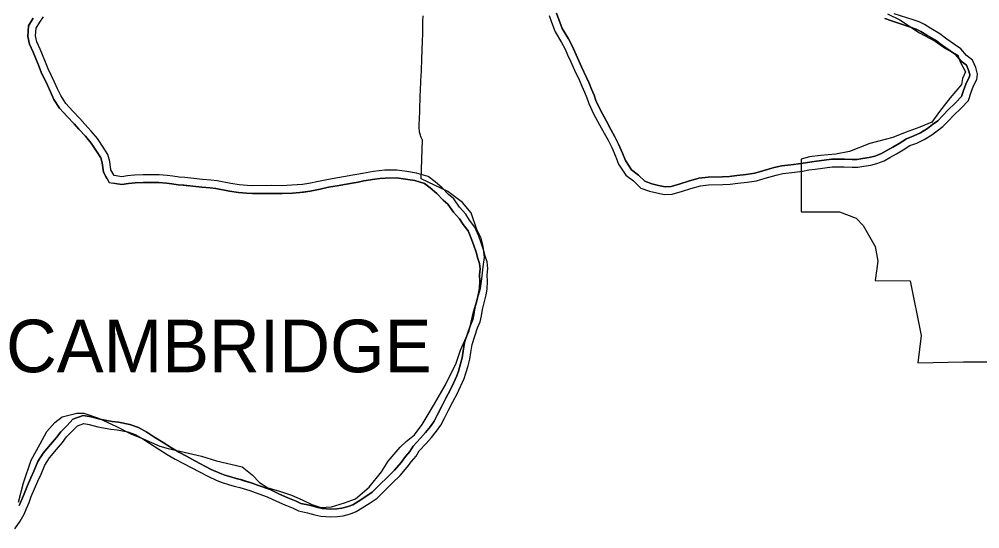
# Model space of a CAD drawing. Extents: x -29.6 to 34, y 0 to 22.
# Drawn here: x -25.281 to -23.658, y 3.715 to 4.576 of the extents above; entities that cross this region are included whole.
import ezdxf

# ---------------------------------------------------------------- set-up
doc = ezdxf.new("R2010")
doc.units = 0
for name, color, linetype in [('GM_X_Corporation', 7, 'Continuous'), ('GM_X_Corporation_Text', 7, 'Continuous'), ('GM_X_Major_River', 7, 'Continuous'), ('GM_X_Minor_River', 7, 'Continuous')]:
    doc.layers.add(name, color=color, linetype=linetype)

msp = doc.modelspace()

# ---------------------------------------------------------------- linework, layer by layer
at = {"layer": 'GM_X_Corporation'}
for points in [[(-25.2827, 3.7602), (-25.2741, 3.7929), (-25.2611, 3.831), (-25.2463, 3.8585), (-25.2346, 3.8795), (-25.2212, 3.8949), (-25.2088, 3.9042), (-25.1951, 3.9076), (-25.1841, 3.9107), (-25.1721, 3.9104), (-25.1473, 3.9021), (-25.1171, 3.888), (-25.0927, 3.8757), (-25.0721, 3.8671), (-25.0439, 3.8549), (-25.0298, 3.8508), (-25.0026, 3.8448), (-24.9734, 3.8377), (-24.9482, 3.8297), (-24.9049, 3.8196), (-24.8878, 3.8065), (-24.8757, 3.7934), (-24.8616, 3.7843), (-24.8434, 3.7793), (-24.8213, 3.7722), (-24.8031, 3.7642), (-24.787, 3.7561), (-24.7719, 3.7511), (-24.7538, 3.7521), (-24.7316, 3.7591), (-24.7132, 3.766), (-24.6903, 3.7853), (-24.6691, 3.8115), (-24.658, 3.8296), (-24.6379, 3.8528), (-24.6278, 3.8629), (-24.6137, 3.874), (-24.6006, 3.8911), (-24.5885, 3.9113), (-24.5795, 3.9264), (-24.5613, 3.9586), (-24.5432, 3.9949), (-24.5361, 4.0171), (-24.521, 4.0493), (-24.514, 4.0816), (-24.5019, 4.1211), (-24.4999, 4.1377), (-24.4973, 4.1579), (-24.4953, 4.1735), (-24.4973, 4.1926), (-24.5009, 4.2062), (-24.5084, 4.2209), (-24.5176, 4.2489), (-24.5322, 4.2665), (-24.5575, 4.285), (-24.6024, 4.3065), (-24.6002, 4.372), (-24.6005, 4.3726), (-24.6013, 4.3741), (-24.6021, 4.3761), (-24.6028, 4.3778), (-24.6035, 4.3799), (-24.604, 4.3816), (-24.6045, 4.3834), (-24.6049, 4.3853), (-24.6053, 4.3884), (-24.6055, 4.3907), (-24.6056, 4.3937), (-24.6056, 4.397), (-24.6055, 4.4007), (-24.6053, 4.4053), (-24.605, 4.4108), (-24.6048, 4.417), (-24.6045, 4.4229), (-24.6043, 4.4309), (-24.6039, 4.4378), (-24.6037, 4.4448), (-24.6027, 4.4698), (-24.6026, 4.4744), (-24.6024, 4.4786), (-24.6019, 4.4901), (-24.6012, 4.5081), (-24.6007, 4.5243), (-24.6002, 4.5385), (-24.5997, 4.5516), (-24.5995, 4.5637), (-24.5992, 4.5728), (-24.5989, 4.5818)], [(-23.8145, 4.5853), (-23.7934, 4.5751), (-23.7604, 4.5531), (-23.7338, 4.539), (-23.7165, 4.5265), (-23.6953, 4.5151), (-23.6914, 4.5041), (-23.6828, 4.4869), (-23.6875, 4.4759), (-23.6891, 4.4657), (-23.7087, 4.443), (-23.7267, 4.4202), (-23.7392, 4.4022), (-23.7596, 4.3935), (-23.7847, 4.3849), (-23.8051, 4.3763), (-23.8443, 4.3661), (-23.8788, 4.3527), (-23.9015, 4.348), (-23.9274, 4.3457), (-23.9462, 4.3433), (-23.9601, 4.3396), (-23.9601, 4.2508), (-23.8952, 4.2508), (-23.8674, 4.2397), (-23.8554, 4.2273), (-23.8353, 4.1923), (-23.8307, 4.1673), (-23.8354, 4.1346), (-23.776, 4.134), (-23.7577, 4.0418), (-23.7628, 3.9956), (-23.6858, 3.997), (-23.6371, 3.9973)]]:
    msp.add_lwpolyline(points, dxfattribs=at)
at = {"layer": 'GM_X_Major_River'}
for points in [[(-25.1327, 4.3056), (-25.1392, 4.3176), (-25.1413, 4.3332), (-25.1438, 4.3419), (-25.1506, 4.3529), (-25.1598, 4.3666), (-25.1695, 4.3782), (-25.1805, 4.3902), (-25.1885, 4.3995), (-25.2005, 4.4114), (-25.2133, 4.4255), (-25.2229, 4.4406), (-25.2287, 4.4532), (-25.2337, 4.4644), (-25.2442, 4.4866), (-25.2491, 4.4982), (-25.2541, 4.5107), (-25.258, 4.5203), (-25.2642, 4.5337), (-25.2671, 4.5469), (-25.2658, 4.5648), (-25.2577, 4.578)], [(-25.2577, 4.578), (-25.2658, 4.5648), (-25.2671, 4.5469), (-25.2642, 4.5337), (-25.258, 4.5203), (-25.2541, 4.5107), (-25.2491, 4.4982), (-25.2442, 4.4866), (-25.2337, 4.4644), (-25.2287, 4.4532), (-25.2229, 4.4406), (-25.2133, 4.4255), (-25.2005, 4.4114), (-25.1885, 4.3995), (-25.1805, 4.3902), (-25.1695, 4.3782), (-25.1598, 4.3666), (-25.1506, 4.3529), (-25.1438, 4.3419), (-25.1413, 4.3332), (-25.1392, 4.3176), (-25.1296, 4.2999)], [(-25.1212, 4.3118), (-25.1266, 4.3217), (-25.1285, 4.3359), (-25.1317, 4.3473), (-25.1396, 4.36), (-25.1493, 4.3745), (-25.1597, 4.3868), (-25.1707, 4.3988), (-25.1789, 4.4084), (-25.1911, 4.4204), (-25.2028, 4.4334), (-25.2114, 4.4469), (-25.2168, 4.4586), (-25.2219, 4.4699), (-25.2323, 4.4919), (-25.237, 4.5032), (-25.242, 4.5156), (-25.246, 4.5255), (-25.2518, 4.5379), (-25.2539, 4.5478), (-25.253, 4.5606), (-25.2467, 4.571), (-25.2407, 4.5799)], [(-24.3858, 4.5822), (-24.3818, 4.5708), (-24.3757, 4.5549), (-24.3649, 4.5365), (-24.3592, 4.5255), (-24.3549, 4.5156), (-24.3502, 4.5053), (-24.343, 4.4901), (-24.3347, 4.4724), (-24.3308, 4.4628), (-24.3264, 4.4529), (-24.3225, 4.443), (-24.3192, 4.4338), (-24.3109, 4.4164), (-24.3009, 4.3973), (-24.293, 4.3835), (-24.2865, 4.3715), (-24.2804, 4.3591), (-24.274, 4.3449), (-24.2689, 4.3314), (-24.2564, 4.3123), (-24.2436, 4.3028), (-24.2314, 4.2908), (-24.2165, 4.2856), (-24.2041, 4.2825), (-24.1913, 4.2798), (-24.1779, 4.2802), (-24.1609, 4.2853), (-24.1467, 4.29), (-24.1305, 4.2944), (-24.1167, 4.2963), (-24.0926, 4.2965), (-24.0802, 4.2973), (-24.0674, 4.2988), (-24.0515, 4.3007), (-24.0359, 4.3029), (-24.0211, 4.3073), (-24.0027, 4.3128), (-23.991, 4.3153), (-23.9758, 4.3169), (-23.9581, 4.3195), (-23.9475, 4.3213), (-23.9365, 4.3228), (-23.9078, 4.3266), (-23.8976, 4.3267), (-23.8876, 4.3264), (-23.8742, 4.3258), (-23.8646, 4.3262), (-23.8543, 4.3277), (-23.8427, 4.3296), (-23.8321, 4.3321), (-23.82, 4.3368), (-23.8102, 4.3422), (-23.7989, 4.3484), (-23.7876, 4.3552), (-23.7766, 4.3624), (-23.7646, 4.3667), (-23.7523, 4.3729), (-23.7396, 4.3808), (-23.7304, 4.3876), (-23.7209, 4.3948), (-23.7114, 4.4044), (-23.7029, 4.4134), (-23.6899, 4.4256), (-23.6776, 4.4388), (-23.6731, 4.453), (-23.6689, 4.4637), (-23.6633, 4.4744), (-23.662, 4.4833), (-23.6649, 4.4947), (-23.6706, 4.5067), (-23.6806, 4.5145), (-23.6906, 4.5261), (-23.7009, 4.5331), (-23.7138, 4.5423), (-23.7259, 4.5514), (-23.7412, 4.5602), (-23.7518, 4.5669), (-23.7611, 4.5714), (-23.771, 4.5749), (-23.803, 4.5853)], [(-24.3734, 4.5864), (-24.3696, 4.5753), (-24.3639, 4.5605), (-24.3535, 4.5428), (-24.3474, 4.5311), (-24.3429, 4.5209), (-24.3383, 4.5108), (-24.3312, 4.4956), (-24.3228, 4.4776), (-24.3187, 4.4679), (-24.3144, 4.4579), (-24.3102, 4.4476), (-24.3071, 4.4388), (-24.2993, 4.4223), (-24.2894, 4.4036), (-24.2816, 4.3898), (-24.2749, 4.3774), (-24.2686, 4.3647), (-24.2619, 4.3499), (-24.2572, 4.3374), (-24.2467, 4.3214), (-24.235, 4.3128), (-24.2243, 4.3022), (-24.2128, 4.2981), (-24.2011, 4.2952), (-24.1901, 4.2929), (-24.18, 4.2932), (-24.1648, 4.2978), (-24.1505, 4.3025), (-24.1331, 4.3072), (-24.1176, 4.3093), (-24.093, 4.3095), (-24.0814, 4.3103), (-24.069, 4.3118), (-24.0532, 4.3136), (-24.0387, 4.3157), (-24.0248, 4.3198), (-24.006, 4.3254), (-23.9931, 4.3282), (-23.9774, 4.3298), (-23.9602, 4.3324), (-23.9495, 4.3342), (-23.9382, 4.3358), (-23.9087, 4.3396), (-23.8974, 4.3397), (-23.8872, 4.3394), (-23.8742, 4.3388), (-23.8658, 4.3392), (-23.8563, 4.3406), (-23.8452, 4.3424), (-23.836, 4.3446), (-23.8256, 4.3487), (-23.8164, 4.3537), (-23.8054, 4.3597), (-23.7945, 4.3662), (-23.7825, 4.3741), (-23.7698, 4.3788), (-23.7586, 4.3843), (-23.7469, 4.3916), (-23.7382, 4.398), (-23.7295, 4.4046), (-23.7208, 4.4135), (-23.7122, 4.4226), (-23.6992, 4.4348), (-23.6892, 4.4455), (-23.6854, 4.4574), (-23.6808, 4.4691), (-23.6759, 4.4785), (-23.6753, 4.4827), (-23.6772, 4.4902), (-23.6811, 4.4983), (-23.6897, 4.5049), (-23.6994, 4.5163), (-23.7084, 4.5224), (-23.7215, 4.5318), (-23.7331, 4.5405), (-23.7479, 4.549), (-23.7582, 4.5554), (-23.7661, 4.5594), (-23.7752, 4.5625), (-23.8074, 4.573), (-23.8188, 4.5774)], [(-23.8188, 4.5774), (-23.8074, 4.573), (-23.7752, 4.5625), (-23.7661, 4.5594), (-23.7582, 4.5554), (-23.7479, 4.549), (-23.7331, 4.5405), (-23.7215, 4.5318), (-23.7084, 4.5224), (-23.6994, 4.5163), (-23.6897, 4.5049), (-23.6811, 4.4983), (-23.6772, 4.4902), (-23.6753, 4.4827), (-23.6759, 4.4785), (-23.6808, 4.4691), (-23.6854, 4.4574), (-23.6892, 4.4455), (-23.6992, 4.4348), (-23.7122, 4.4226), (-23.7208, 4.4135), (-23.7295, 4.4046), (-23.7382, 4.398), (-23.7469, 4.3916), (-23.7586, 4.3843), (-23.7698, 4.3788), (-23.7825, 4.3741), (-23.7945, 4.3662), (-23.8054, 4.3597), (-23.8164, 4.3537), (-23.8256, 4.3487), (-23.836, 4.3446), (-23.8452, 4.3424), (-23.8563, 4.3406), (-23.8658, 4.3392), (-23.8742, 4.3388), (-23.8872, 4.3394), (-23.8974, 4.3397), (-23.9087, 4.3396), (-23.9382, 4.3358), (-23.9495, 4.3342), (-23.9602, 4.3324), (-23.9774, 4.3298), (-23.9931, 4.3282), (-24.006, 4.3254), (-24.0248, 4.3198), (-24.0387, 4.3157), (-24.0532, 4.3136), (-24.069, 4.3118), (-24.0814, 4.3103), (-24.093, 4.3095), (-24.1176, 4.3093), (-24.1331, 4.3072), (-24.1505, 4.3025), (-24.1648, 4.2978), (-24.18, 4.2932), (-24.1901, 4.2929), (-24.2011, 4.2952), (-24.2128, 4.2981), (-24.2243, 4.3022), (-24.235, 4.3128), (-24.2467, 4.3214), (-24.2572, 4.3374), (-24.2619, 4.3499), (-24.2686, 4.3647), (-24.2749, 4.3774), (-24.2816, 4.3898), (-24.2894, 4.4036), (-24.2993, 4.4223), (-24.3071, 4.4388), (-24.3102, 4.4476), (-24.3144, 4.4579), (-24.3187, 4.4679), (-24.3228, 4.4776), (-24.3312, 4.4956), (-24.3383, 4.5108), (-24.3429, 4.5209), (-24.3474, 4.5311), (-24.3535, 4.5428), (-24.3639, 4.5605), (-24.3696, 4.5753), (-24.3734, 4.5864)], [(-24.9089, 3.785), (-24.8919, 3.7798), (-24.883, 3.7767), (-24.8624, 3.7694), (-24.8468, 3.762), (-24.8326, 3.7557), (-24.8187, 3.7498), (-24.8098, 3.7456), (-24.7942, 3.7421), (-24.7821, 3.739), (-24.7719, 3.7366), (-24.7552, 3.7353), (-24.7435, 3.7361), (-24.734, 3.7373), (-24.7219, 3.7402), (-24.712, 3.7442), (-24.7018, 3.7503), (-24.6887, 3.7589), (-24.6768, 3.7671), (-24.6627, 3.7811), (-24.6511, 3.7922), (-24.638, 3.8054), (-24.6261, 3.819), (-24.6184, 3.829), (-24.611, 3.838), (-24.6054, 3.8469), (-24.5938, 3.8594), (-24.585, 3.8694), (-24.5762, 3.8801), (-24.5692, 3.8901), (-24.5629, 3.9023), (-24.5562, 3.9154), (-24.5489, 3.9297), (-24.5415, 3.9433), (-24.5356, 3.9557), (-24.5297, 3.9689), (-24.5269, 3.9778), (-24.5231, 3.9903), (-24.5203, 4.0017), (-24.5186, 4.0131), (-24.5162, 4.0266), (-24.5069, 4.0547), (-24.5027, 4.065), (-24.5006, 4.0747), (-24.4986, 4.0857), (-24.4958, 4.0971), (-24.4924, 4.1102), (-24.491, 4.1202), (-24.49, 4.1334), (-24.4905, 4.1437), (-24.4895, 4.1547), (-24.491, 4.166), (-24.4939, 4.1756), (-24.4971, 4.1866), (-24.5011, 4.1983), (-24.5051, 4.2093), (-24.5116, 4.2249), (-24.5205, 4.2365), (-24.527, 4.2468), (-24.5377, 4.2584), (-24.5473, 4.2726), (-24.5562, 4.28), (-24.567, 4.2909), (-24.5787, 4.3015), (-24.5905, 4.3103), (-24.61, 4.3162), (-24.6267, 4.3189), (-24.6433, 4.3209), (-24.6639, 4.3208), (-24.6734, 4.3196), (-24.6826, 4.3185), (-24.7014, 4.3155), (-24.711, 4.3137), (-24.7212, 4.3118), (-24.7304, 4.3103), (-24.7467, 4.3074), (-24.7616, 4.3048), (-24.7757, 4.3018), (-24.7923, 4.2985), (-24.8026, 4.297), (-24.8207, 4.2955), (-24.8377, 4.2946), (-24.8547, 4.2949), (-24.8869, 4.2946), (-24.8965, 4.2949), (-24.9096, 4.2963), (-24.9238, 4.2983), (-24.9472, 4.3031), (-24.9575, 4.3041), (-24.9717, 4.3051), (-24.9866, 4.3067), (-25.0018, 4.3084), (-25.0114, 4.3094), (-25.022, 4.3107), (-25.0312, 4.3121), (-25.0451, 4.3131), (-25.072, 4.3132), (-25.0865, 4.3128), (-25.0985, 4.3112), (-25.1081, 4.3098), (-25.1212, 4.3118)], [(-25.1296, 4.2999), (-25.1081, 4.2965), (-25.0967, 4.2983), (-25.0855, 4.2997), (-25.0718, 4.3002), (-25.0456, 4.3), (-25.0326, 4.2991), (-25.0238, 4.2978), (-25.0129, 4.2964), (-25.0032, 4.2954), (-24.988, 4.2937), (-24.9728, 4.292), (-24.9586, 4.2911), (-24.9491, 4.2902), (-24.926, 4.2854), (-24.9112, 4.2833), (-24.8973, 4.2819), (-24.8871, 4.2816), (-24.8547, 4.2818), (-24.8374, 4.2816), (-24.8198, 4.2824), (-24.8011, 4.284), (-24.7901, 4.2856), (-24.7731, 4.289), (-24.7591, 4.292), (-24.7444, 4.2945), (-24.7282, 4.2975), (-24.719, 4.299), (-24.7086, 4.3008), (-24.6991, 4.3027), (-24.6808, 4.3056), (-24.6719, 4.3067), (-24.6631, 4.3077), (-24.6441, 4.3078), (-24.6285, 4.306), (-24.6129, 4.3034), (-24.5964, 4.2984), (-24.587, 4.2914), (-24.576, 4.2815), (-24.5651, 4.2704), (-24.5571, 4.2637), (-24.5479, 4.2503), (-24.5374, 4.2388), (-24.5312, 4.2291), (-24.523, 4.2183), (-24.5173, 4.2045), (-24.5134, 4.194), (-24.5096, 4.1826), (-24.5064, 4.1719), (-24.5038, 4.1633), (-24.5026, 4.1544), (-24.5036, 4.144), (-24.5031, 4.1336), (-24.504, 4.1216), (-24.5052, 4.1128), (-24.5085, 4.1003), (-24.5114, 4.0884), (-24.5134, 4.0772), (-24.5152, 4.0689), (-24.5191, 4.0592), (-24.5289, 4.0298), (-24.5315, 4.0152), (-24.5332, 4.0042), (-24.5357, 3.9937), (-24.5394, 3.9817), (-24.5419, 3.9736), (-24.5475, 3.9612), (-24.5532, 3.9492), (-24.5604, 3.9358), (-24.5679, 3.9214), (-24.5745, 3.9082), (-24.5804, 3.8969), (-24.5866, 3.888), (-24.5949, 3.8779), (-24.6035, 3.8681), (-24.6158, 3.8549), (-24.6216, 3.8456), (-24.6286, 3.8372), (-24.6362, 3.8273), (-24.6476, 3.8143), (-24.6602, 3.8015), (-24.6718, 3.7905), (-24.6851, 3.7772), (-24.696, 3.7697), (-24.7087, 3.7613), (-24.7178, 3.7559), (-24.7259, 3.7526), (-24.7363, 3.7501), (-24.7447, 3.7491), (-24.7551, 3.7484), (-24.7698, 3.7496), (-24.779, 3.7517), (-24.7912, 3.7549), (-24.8056, 3.758), (-24.8134, 3.7617), (-24.8274, 3.7677), (-24.8414, 3.7739), (-24.8575, 3.7815), (-24.8787, 3.789), (-24.8878, 3.7922), (-24.9054, 3.7976)], [(-24.9051, 3.7975), (-24.8878, 3.7922), (-24.8787, 3.789), (-24.8575, 3.7815), (-24.8414, 3.7739), (-24.8274, 3.7677), (-24.8134, 3.7617), (-24.8056, 3.758), (-24.7912, 3.7549), (-24.779, 3.7517), (-24.7698, 3.7496), (-24.7551, 3.7484), (-24.7447, 3.7491), (-24.7363, 3.7501), (-24.7259, 3.7526), (-24.7178, 3.7559), (-24.7087, 3.7613), (-24.696, 3.7697), (-24.6851, 3.7772), (-24.6718, 3.7905), (-24.6602, 3.8015), (-24.6476, 3.8143), (-24.6362, 3.8273), (-24.6286, 3.8372), (-24.6216, 3.8456), (-24.6158, 3.8549), (-24.6035, 3.8681), (-24.5949, 3.8779), (-24.5866, 3.888), (-24.5804, 3.8969), (-24.5745, 3.9082), (-24.5679, 3.9214), (-24.5604, 3.9358), (-24.5532, 3.9492), (-24.5475, 3.9612), (-24.5419, 3.9736), (-24.5394, 3.9817), (-24.5357, 3.9937), (-24.5332, 4.0042), (-24.5315, 4.0152), (-24.5289, 4.0298), (-24.5191, 4.0592), (-24.5152, 4.0689), (-24.5134, 4.0772), (-24.5114, 4.0884), (-24.5085, 4.1003), (-24.5052, 4.1128), (-24.504, 4.1216), (-24.5031, 4.1336), (-24.5036, 4.144), (-24.5026, 4.1544), (-24.5038, 4.1633), (-24.5064, 4.1719), (-24.5096, 4.1826), (-24.5134, 4.194), (-24.5173, 4.2045), (-24.523, 4.2183), (-24.5312, 4.2291), (-24.5374, 4.2388), (-24.5479, 4.2503), (-24.5571, 4.2637), (-24.5651, 4.2704), (-24.576, 4.2815), (-24.587, 4.2914), (-24.5964, 4.2984), (-24.6129, 4.3034), (-24.6285, 4.306), (-24.6441, 4.3078), (-24.6631, 4.3077), (-24.6719, 4.3067), (-24.6808, 4.3056), (-24.6991, 4.3027), (-24.7086, 4.3008), (-24.719, 4.299), (-24.7282, 4.2975), (-24.7444, 4.2945), (-24.7591, 4.292), (-24.7731, 4.289), (-24.7901, 4.2856), (-24.8011, 4.284), (-24.8198, 4.2824), (-24.8374, 4.2816), (-24.8547, 4.2818), (-24.8871, 4.2816), (-24.8973, 4.2819), (-24.9112, 4.2833), (-24.926, 4.2854), (-24.9491, 4.2902), (-24.9586, 4.2911), (-24.9728, 4.292), (-24.988, 4.2937), (-25.0032, 4.2954), (-25.0129, 4.2964), (-25.0238, 4.2978), (-25.0326, 4.2991), (-25.0456, 4.3), (-25.0718, 4.3002), (-25.0855, 4.2997), (-25.0967, 4.2983), (-25.1081, 4.2965), (-25.1232, 4.2989)], [(-25.2815, 3.7543), (-25.2769, 3.7644), (-25.2732, 3.7745), (-25.2674, 3.7881), (-25.2618, 3.801), (-25.2566, 3.8126), (-25.2499, 3.829), (-25.2408, 3.8427), (-25.2286, 3.8577), (-25.2183, 3.8692), (-25.2114, 3.8789), (-25.2007, 3.8894), (-25.1907, 3.9005), (-25.1733, 3.9068), (-25.16, 3.9043), (-25.1455, 3.9002), (-25.1245, 3.8966), (-25.1138, 3.8952), (-25.0943, 3.8915), (-25.0799, 3.8863), (-25.0657, 3.8785), (-25.054, 3.8705), (-25.0384, 3.8608), (-25.0244, 3.8518), (-25.0118, 3.8444), (-24.9988, 3.8378), (-24.9845, 3.8301), (-24.9572, 3.8156), (-24.9422, 3.8089), (-24.9342, 3.8057), (-24.9241, 3.8028), (-24.9147, 3.8), (-24.9056, 3.7977)], [(-24.9054, 3.7976), (-24.9147, 3.8), (-24.9241, 3.8028), (-24.9342, 3.8057), (-24.9422, 3.8089), (-24.9572, 3.8156), (-24.9845, 3.8301), (-24.9988, 3.8378), (-25.0118, 3.8444), (-25.0244, 3.8518), (-25.0384, 3.8608), (-25.054, 3.8705), (-25.0657, 3.8785), (-25.0799, 3.8863), (-25.0943, 3.8915), (-25.1138, 3.8952), (-25.1245, 3.8966), (-25.1455, 3.9002), (-25.16, 3.9043), (-25.1733, 3.9068), (-25.1907, 3.9005), (-25.2007, 3.8894), (-25.2114, 3.8789), (-25.2183, 3.8692), (-25.2286, 3.8577), (-25.2408, 3.8427), (-25.2499, 3.829), (-25.2566, 3.8126), (-25.2618, 3.801), (-25.2674, 3.7881), (-25.2732, 3.7745), (-25.2769, 3.7644), (-25.2815, 3.7543)], [(-25.2887, 3.7152), (-25.2799, 3.728), (-25.2729, 3.7398), (-25.2694, 3.7494), (-25.2649, 3.7594), (-25.261, 3.7697), (-25.2554, 3.7829), (-25.2499, 3.7957), (-25.2446, 3.8075), (-25.2384, 3.8228), (-25.2303, 3.835), (-25.2187, 3.8493), (-25.2081, 3.861), (-25.2015, 3.8703), (-25.1913, 3.8804), (-25.1832, 3.8893), (-25.1722, 3.8933), (-25.163, 3.8916), (-25.1484, 3.8874), (-25.1265, 3.8837), (-25.1158, 3.8823), (-25.0977, 3.8789), (-25.0853, 3.8744), (-25.0725, 3.8673), (-25.0611, 3.8596), (-25.0454, 3.8498), (-25.0312, 3.8406), (-25.018, 3.8329), (-25.0049, 3.8263), (-24.9907, 3.8185), (-24.9629, 3.8038), (-24.9473, 3.7968), (-24.9384, 3.7933), (-24.9278, 3.7902), (-24.9182, 3.7874), (-24.9089, 3.785)]]:
    msp.add_lwpolyline(points, dxfattribs=at)
at = {"layer": 'GM_X_Minor_River'}
for p, q in [((-24.9947, 4.2937), (-25.0091, 4.2957)), ((-24.7901, 4.2856), (-24.8072, 4.2835))]:
    msp.add_line(p, q, dxfattribs=at)

# ---------------------------------------------------------------- texts
at = {"layer": 'GM_X_Corporation_Text'}
msp.add_text('CAMBRIDGE', height=0.08878, rotation=0, dxfattribs=at).set_placement((-25.3037, 3.9796))

doc.saveas('drawing.dxf')
